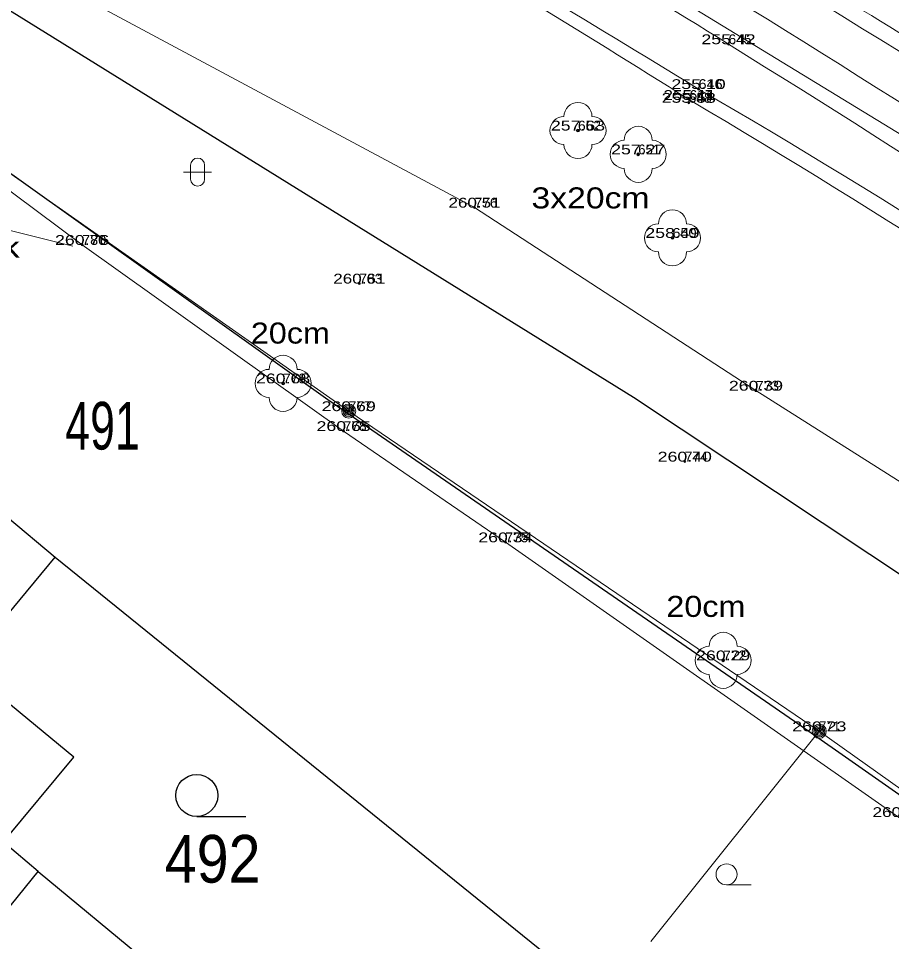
# Model space of a CAD drawing. Extents: x -568530 to -568223, y -1154101 to -1153740.
# Drawn here: x -568408.9 to -568377.75, y -1153975.43 to -1153942.5 of the extents above; entities that cross this region are included whole.
import ezdxf
from ezdxf.enums import TextEntityAlignment as Align

# ---------------------------------------------------------------- set-up
doc = ezdxf.new("R2010")
doc.units = 0
doc.header["$LTSCALE"] = 0.14
doc.header["$PDMODE"] = 32
doc.header["$PDSIZE"] = 0.07
for name, color, linetype, lineweight in [('1', 7, 'Continuous', 25), ('11', 7, 'Continuous', 13), ('12', 7, 'Continuous', 13), ('14', 7, 'Continuous', 13), ('22', 7, 'Continuous', 13), ('25', 7, 'Continuous', 13), ('36', 7, 'Continuous', 13), ('4', 7, 'Continuous', 25), ('42', 7, 'Continuous', 13), ('52', 7, 'Continuous', 13), ('53', 7, 'Continuous', 13), ('7', 7, 'Continuous', 13)]:
    doc.layers.add(name, color=color, linetype=linetype, lineweight=lineweight)
doc.layers.add('13', color=7, linetype='Continuous')
doc.layers.add('18', color=7, linetype='Continuous')

msp = doc.modelspace()

# ---------------------------------------------------------------- linework, layer by layer
at = {"layer": '1'}
msp.add_line((-568408.2, -1153972.93), (-568390.78, -1153987.34), dxfattribs=at)
for points in [[(-568421.83, -1153950.13), (-568416.35, -1153942.92), (-568397.86, -1153956.1), (-568381.21, -1153967.57)], [(-568421.83, -1153950.13), (-568427.7, -1153957.09), (-568433.42, -1153964.08), (-568426, -1153970.14), (-568416.24, -1153978.06), (-568413.96, -1153980.06), (-568408.2, -1153972.93), (-568413.31, -1153968.6), (-568420.22, -1153963.08), (-568427.7, -1153957.09)], [(-568414.4, -1153956.01), (-568407.59, -1153961.72), (-568387.94, -1153977.62)], [(-568409.44, -1153971.88), (-568406.92, -1153968.85), (-568410.84, -1153965.63), (-568407.59, -1153961.72)], [(-568381.21, -1153967.57), (-568365.54, -1153978.53), (-568303.79, -1154025.76)]]:
    msp.add_lwpolyline(points, dxfattribs=at)
at = {"layer": '11'}
for centre, radius, start, end in [((-568987.7107, -1154929.3603), 1154.3916, 58.50566, 59.89077), ((-568598.8116, -1154282.7187), 399.3866, 57.62556, 61.60266), ((-568603.2448, -1154307.4258), 428.6782, 55.61365, 58.88779), ((-568594.3404, -1154293.2988), 411.4198, 55.52877, 58.93604), ((-568515.3815, -1154170.2907), 260.4616, 54.55112, 59.87018), ((-568546.6395, -1154219.0038), 317.7953, 55.0507, 59.41916)]:
    msp.add_arc(centre, radius, start, end, dxfattribs=at)
for p in [(-568383.57, -1153943.42), (-568384.64, -1153945.02), (-568384.99, -1153945.51), (-568384.96, -1153945.41), (-568388.94, -1153946.5), (-568386.79, -1153947.35), (-568392.63, -1153949.25), (-568385.57, -1153950.33), (-568406.63, -1153950.58), (-568396.74, -1153951.96), (-568399.46, -1153955.52), (-568382.59, -1153955.78), (-568397.12, -1153956.51), (-568397.3, -1153957.22), (-568385.13, -1153958.31), (-568391.53, -1153961.19), (-568383.76, -1153965.4), (-568380.33, -1153967.93)]:
    msp.add_point(p, dxfattribs=at)
at = {"layer": '12'}
for centre, radius, start, end in [((-568645.0661, -1154364.1594), 495.3805, 58.1384, 61.39848), ((-568708.2241, -1154467.802), 618.2333, 55.97737, 58.24225), ((-568727.54, -1154497.0975), 651.8237, 56.01434, 58.14955)]:
    msp.add_arc(centre, radius, start, end, dxfattribs=at)
at = {"layer": '14'}
msp.add_lwpolyline([(-568415.48, -1153937.58), (-568406.64, -1153941.73), (-568392.63, -1153949.25), (-568382.59, -1153955.78), (-568371.09, -1153963.05), (-568356.19, -1153973.32)], dxfattribs=at)
at = {"layer": '22'}
for centre in [(-568388.94, -1153946.5), (-568386.79, -1153947.35), (-568385.57, -1153950.33), (-568399.46, -1153955.52), (-568383.76, -1153965.4)]:
    msp.add_circle(centre, 0.05, dxfattribs=at)
for centre, start, end in [((-568388.94, -1153946), 0, 180), ((-568389.44, -1153946.5), 90, 270), ((-568388.44, -1153946.5), 270, 90), ((-568386.79, -1153946.85), 0, 180), ((-568387.29, -1153947.35), 90, 270), ((-568386.29, -1153947.35), 270, 90), ((-568388.94, -1153947), 180, 0), ((-568386.79, -1153947.85), 180, 0), ((-568385.57, -1153949.83), 0, 180), ((-568386.07, -1153950.33), 90, 270), ((-568385.07, -1153950.33), 270, 90), ((-568385.57, -1153950.83), 180, 0), ((-568399.46, -1153955.02), 0, 180), ((-568399.96, -1153955.52), 90, 270), ((-568398.96, -1153955.52), 270, 90), ((-568399.46, -1153956.02), 180, 0), ((-568383.76, -1153964.9), 0, 180), ((-568384.26, -1153965.4), 90, 270), ((-568383.26, -1153965.4), 270, 90), ((-568383.76, -1153965.9), 180, 0)]:
    msp.add_arc(centre, 0.5, start, end, dxfattribs=at)
at = {"layer": '25', "lineweight": 25}
msp.add_line((-568402.54, -1153970.97), (-568400.79, -1153970.97), dxfattribs=at)
at = {"layer": '25'}
for centre, radius in [((-568397.12, -1153956.51), 0.25), ((-568397.12, -1153956.51), 0.2), ((-568397.12, -1153956.51), 0.15), ((-568397.12, -1153956.51), 0.1), ((-568397.12, -1153956.51), 0.05), ((-568380.33, -1153967.93), 0.25), ((-568380.33, -1153967.93), 0.2), ((-568380.33, -1153967.93), 0.15), ((-568380.33, -1153967.93), 0.1), ((-568380.33, -1153967.93), 0.05)]:
    msp.add_circle(centre, radius, dxfattribs=at)
at = {"layer": '25', "lineweight": 25}
msp.add_circle((-568402.54, -1153970.22), 0.75, dxfattribs=at)
at = {"layer": '36'}
for p, q in [((-568402.759, -1153947.733), (-568402.759, -1153948.233)), ((-568402.259, -1153947.733), (-568402.259, -1153948.233)), ((-568403.009, -1153947.983), (-568402.009, -1153947.983)), ((-568383.639, -1153973.411), (-568382.764, -1153973.411))]:
    msp.add_line(p, q, dxfattribs=at)
msp.add_circle((-568383.6392, -1153973.0356), 0.375, dxfattribs=at)
for centre, start, end in [((-568402.5083, -1153947.7337), 0, 180), ((-568402.5083, -1153948.2337), 180, 0)]:
    msp.add_arc(centre, 0.25, start, end, dxfattribs=at)
at = {"layer": '4'}
msp.add_lwpolyline([(-568416.35, -1153942.92), (-568411.96, -1153940.51), (-568386.96, -1153956.01), (-568354.94, -1153977.29), (-568293.66, -1154026.45)], dxfattribs=at)
at = {"layer": '42'}
msp.add_line((-568416.092, -1153948.348), (-568406.958, -1153950.624), dxfattribs=at)
at = {"layer": '52'}
for points in [[(-568440.61, -1153926.76), (-568414.88, -1153944.05), (-568397.12, -1153956.51), (-568380.33, -1153967.93), (-568365.972, -1153978.132)], [(-568380.33, -1153967.93), (-568386.339, -1153975.429), (-568386.339, -1153975.429)]]:
    msp.add_lwpolyline(points, dxfattribs=at)
at = {"layer": '53'}
msp.add_lwpolyline([(-568433.578, -1153915.068), (-568419.78, -1153922.17), (-568410.54, -1153927.14), (-568389.55, -1153939.23), (-568371.805, -1153950.061), (-568349.435, -1153965.343)], dxfattribs=at)
at = {"layer": '7'}
for points in [[(-568418.88, -1153947.23), (-568416.54, -1153943.33), (-568413.3, -1153945.67), (-568409.87, -1153948.17), (-568406.63, -1153950.58), (-568397.3, -1153957.22)], [(-568397.3, -1153957.22), (-568391.53, -1153961.19), (-568377.5, -1153970.99), (-568362.5, -1153981.67)]]:
    msp.add_lwpolyline(points, dxfattribs=at)

# ---------------------------------------------------------------- texts
at = {"layer": '12'}
for s, width, p in [('255.42', 1.35, (-568383.57, -1153943.42)), ('255.10', 1.35, (-568384.6395, -1153945.02)), ('255.58', 1.35, (-568384.99, -1153945.51)), ('255.11', 1.3, (-568384.96, -1153945.41)), ('257.63', 1.35, (-568388.94, -1153946.5)), ('257.27', 1.35, (-568386.79, -1153947.35)), ('260.51', 1.3, (-568392.63, -1153949.25)), ('258.49', 1.35, (-568385.57, -1153950.33)), ('260.76', 1.35, (-568406.63, -1153950.58)), ('260.61', 1.3, (-568396.74, -1153951.96)), ('260.68', 1.35, (-568399.46, -1153955.52)), ('260.39', 1.35, (-568382.59, -1153955.78)), ('260.69', 1.35, (-568397.12, -1153956.51)), ('260.65', 1.35, (-568397.3005, -1153957.22)), ('260.40', 1.35, (-568385.1295, -1153958.31)), ('260.34', 1.35, (-568391.53, -1153961.19)), ('260.29', 1.35, (-568383.76, -1153965.4)), ('260.23', 1.35, (-568380.33, -1153967.93)), ('260.01', 1.3, (-568377.5, -1153970.99))]:
    msp.add_text(s, height=0.35, dxfattribs=dict(at, width=width)).set_placement(p, align=Align.CENTER)
at = {"layer": '13'}
for s, width, p in [('645', 1.05, (-568383.57, -1153943.42)), ('646', 1.1, (-568384.64, -1153945.02)), ('648', 1.05, (-568384.99, -1153945.51)), ('647', 1.05, (-568384.96, -1153945.41)), ('652', 1.05, (-568388.94, -1153946.5)), ('776', 1.05, (-568392.63, -1153949.25)), ('650', 1.1, (-568385.57, -1153950.33)), ('780', 1.1, (-568406.63, -1153950.58)), ('783', 1.05, (-568396.74, -1153951.96)), ('779', 1.05, (-568399.46, -1153955.52)), ('773', 1.05, (-568382.59, -1153955.78)), ('777', 1.05, (-568397.12, -1153956.51)), ('778', 1.05, (-568397.3, -1153957.22)), ('774', 1.05, (-568385.13, -1153958.31)), ('775', 1.05, (-568391.53, -1153961.19)), ('772', 1.05, (-568383.76, -1153965.4)), ('771', 0.95, (-568380.33, -1153967.93))]:
    msp.add_text(s, height=0.35, dxfattribs=dict(at, width=width)).set_placement(p)
msp.add_text('651', height=0.35, dxfattribs=at).set_placement((-568386.79, -1153947.35))
at = {"layer": '18'}
for s, width, p in [('491', 0.7, (-568407.23, -1153957.88)), ('492', 0.9, (-568403.68, -1153973.33))]:
    msp.add_text(s, height=1.7, dxfattribs=dict(at, width=width)).set_placement(p)
at = {"layer": '42'}
for s, width, p in [('3x20cm', 1.2, (-568388.493, -1153949.279)), ('4x bet.sloupek', 1.3, (-568413.0565, -1153951.039)), ('20cm', 1.15, (-568399.201, -1153954.101)), ('20cm', 1.15, (-568384.378, -1153963.851))]:
    msp.add_text(s, height=0.75, dxfattribs=dict(at, width=width)).set_placement(p, align=Align.CENTER)

doc.saveas('drawing.dxf')
